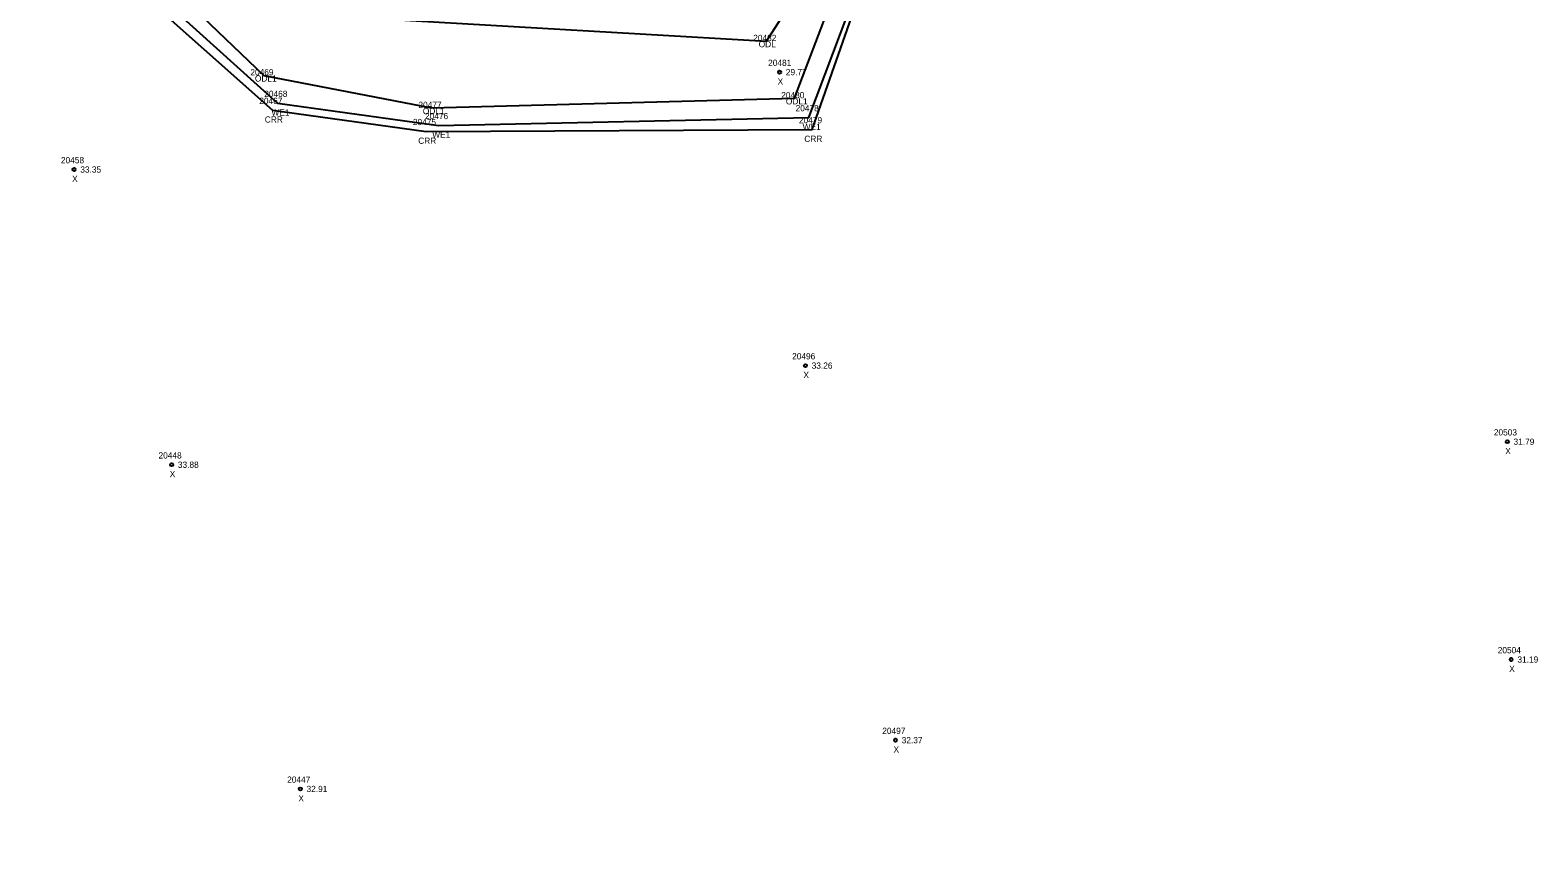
# Model space of a CAD drawing. Extents: x 2445178 to 2446260, y 791158 to 792318.
# Drawn here: x 2445997.4 to 2446239.5, y 791810 to 791939.9 of the extents above; entities that cross this region are included whole.
import ezdxf

# ---------------------------------------------------------------- set-up
doc = ezdxf.new("R2010")
doc.units = 0
for name, color, linetype in [('RD_EX_H2O', 7, 'Continuous'), ('RD_EX_H2O_txCode', 7, 'Continuous'), ('RD_Sketch8', 7, 'Continuous'), ('RD_SMD_Locator', 7, 'Continuous')]:
    doc.layers.add(name, color=color, linetype=linetype)

msp = doc.modelspace()

# ---------------------------------------------------------------- linework, layer by layer
at = {"layer": 'RD_EX_H2O'}
for points in [[(2445756.08, 791812.92), (2445785.69, 791811.94), (2445827.07, 791827.18), (2445867.4, 791836.35), (2445869.07, 791850.26), (2445862.28, 791889.54), (2445866.87, 791900.55), (2445904.83, 791930.74), (2445929.24, 791934.15), (2445984.41, 791970.25), (2446004.58, 791971.21), (2446054.77, 791941.67), (2446115.62, 791938.17), (2446120.64, 791945.97), (2446127.84, 791972.01), (2446160.1, 791969.34), (2446190.11, 792012.94)], [(2445748.32, 791780.49), (2445788.24, 791788.44), (2445846, 791811.01), (2445891.85, 791826.96), (2445872.2, 791885.31), (2445911.58, 791917.24), (2445942.41, 791930.41), (2445989.95, 791963.2), (2446004.43, 791957.67), (2446037.13, 791928.19), (2446062.94, 791924.63), (2446122.42, 791925.89), (2446133.98, 791956.62), (2446163.05, 791958.48), (2446202.11, 792005.16)], [(2445752.43, 791785.31), (2445788.27, 791790.61), (2445845.46, 791813.31), (2445889.72, 791828.98), (2445868.44, 791886.37), (2445910.27, 791920.69), (2445939.62, 791931.64), (2445988.31, 791964.33), (2446005.31, 791961.03), (2446034.89, 791932.66), (2446061.86, 791927.42), (2446120.16, 791928.99), (2446131.56, 791958.98), (2446161.23, 791962.03), (2446198.32, 792006.02)], [(2445746.88, 791778.25), (2445790.91, 791782.86), (2445846.87, 791809.11), (2445896.01, 791824.25), (2445877, 791883.78), (2445912.26, 791916.16), (2445942.78, 791927.77), (2445991.6, 791962.06), (2446003.69, 791956.06), (2446036.32, 791927.07), (2446060.96, 791923.67), (2446122.97, 791923.97), (2446134.24, 791956.18), (2446163.21, 791958.01), (2446202.51, 792004.24)]]:
    msp.add_lwpolyline(points, dxfattribs=at)
at = {"layer": 'RD_SMD_Locator'}
for centre, radius in [((2446115.62, 791938.17), 0.001), ((2446034.89, 791932.66), 0.001), ((2446117.74, 791933.18), 0.25), ((2446037.13, 791928.19), 0.001), ((2446061.86, 791927.42), 0.001), ((2446120.16, 791928.99), 0.001), ((2446036.32, 791927.07), 0.001), ((2446122.42, 791925.89), 0.001), ((2446060.96, 791923.67), 0.001), ((2446062.94, 791924.63), 0.001), ((2446122.97, 791923.97), 0.001), ((2446004.44, 791917.54), 0.25), ((2446121.89, 791886.05), 0.25), ((2446234.6, 791873.83), 0.25), ((2446020.11, 791870.13), 0.25), ((2446235.23, 791838.85), 0.25), ((2446136.35, 791825.9), 0.25), ((2446040.77, 791818.06), 0.25)]:
    msp.add_circle(centre, radius, dxfattribs=at)

# ---------------------------------------------------------------- texts
at = {"layer": 'RD_EX_H2O_txCode'}
for s, p in [('20482', (2446113.5, 791938.17)), ('ODL', (2446114.38, 791937.17)), ('20469', (2446032.75, 791932.66)), ('ODL1', (2446033.48, 791931.66)), ('20468', (2446034.98, 791929.19)), ('20480', (2446118, 791928.99)), ('20467', (2446034.18, 791928.07)), ('20477', (2446059.74, 791927.42)), ('ODL1', (2446060.45, 791926.42)), ('ODL1', (2446118.75, 791927.99)), ('20478', (2446120.31, 791926.89)), ('CRR', (2446035.07, 791925.07)), ('WE1', (2446036.14, 791926.19)), ('20475', (2446058.85, 791924.67)), ('20476', (2446060.8, 791925.63)), ('20479', (2446120.85, 791924.97)), ('CRR', (2446059.71, 791921.67)), ('WE1', (2446061.96, 791922.63)), ('WE1', (2446121.44, 791923.89)), ('CRR', (2446121.71, 791921.97))]:
    msp.add_text(s, height=1, dxfattribs=at).set_placement(p)
at = {"layer": 'RD_Sketch8'}
for s, p in [('20481', (2446115.9, 791934.18)), ('29.77', (2446118.74, 791932.68)), ('X', (2446117.42, 791931.18)), ('20458', (2446002.33, 791918.54)), ('33.35', (2446005.44, 791917.04)), ('X', (2446004.13, 791915.54)), ('20496', (2446119.75, 791887.05)), ('33.26', (2446122.89, 791885.55)), ('X', (2446121.57, 791884.05)), ('20503', (2446232.44, 791874.83)), ('31.79', (2446235.6, 791873.33)), ('20448', (2446018, 791871.13)), ('X', (2446234.28, 791871.83)), ('33.88', (2446021.11, 791869.63)), ('X', (2446019.8, 791868.13)), ('20504', (2446233.07, 791839.85)), ('X', (2446234.91, 791836.85)), ('31.19', (2446236.23, 791838.35)), ('20497', (2446134.23, 791826.9)), ('32.37', (2446137.35, 791825.4)), ('X', (2446136.04, 791823.9)), ('20447', (2446038.66, 791819.06)), ('32.91', (2446041.77, 791817.56)), ('X', (2446040.46, 791816.06))]:
    msp.add_text(s, height=1, dxfattribs=at).set_placement(p)

doc.saveas('drawing.dxf')
